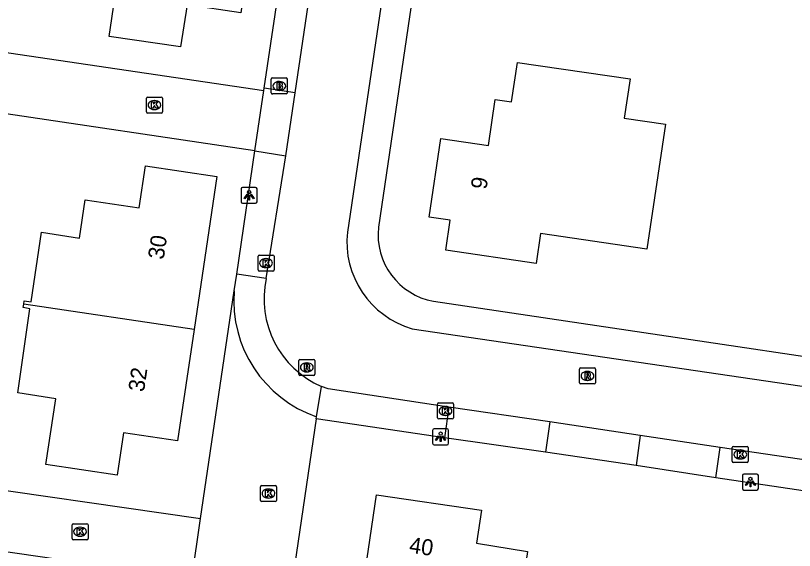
# Model space of a CAD drawing. Extents: x 164150 to 165261, y 382513 to 383432.
# Drawn here: x 164528.83 to 164577.45, y 383053.88 to 383087.26 of the extents above; entities that cross this region are included whole.
import ezdxf

# ---------------------------------------------------------------- set-up
doc = ezdxf.new("R2010")
doc.units = 0
for name, color, linetype in [('IMGEO_Brandkraan', 7, 'Continuous'), ('IMGEO_Kolk', 7, 'Continuous'), ('IMGEO_Lichtpunt', 7, 'Continuous'), ('IMGEO_Pand', 7, 'Continuous'), ('IMGEO_Pand_nummerreeks', 7, 'Continuous'), ('IMGEO_Parkeervlak_open', 7, 'Continuous'), ('IMGEO_Rijbaan_lokaal_open', 7, 'Continuous'), ('IMGEO_Rioolput', 7, 'Continuous'), ('IMGEO_Voetpad_gesloten', 7, 'Continuous'), ('IMGEO_Voetpad_open', 7, 'Continuous')]:
    doc.layers.add(name, color=color, linetype=linetype)

msp = doc.modelspace()

# ---------------------------------------------------------------- linework, layer by layer
at = {"layer": 'IMGEO_Brandkraan'}
for p, q in [((164544.79, 383082.444), (164544.79, 383083.296)), ((164544.865, 383083.37), (164545.717, 383083.37)), ((164545.791, 383083.296), (164545.791, 383082.444)), ((164545.278, 383083.15), (164545.303, 383083.15)), ((164545.717, 383082.37), (164544.865, 383082.37)), ((164545.301, 383082.59), (164545.276, 383082.59))]:
    msp.add_line(p, q, dxfattribs=at)
for points in [[(164544.79, 383082.444), (164544.79, 383083.296)], [(164544.865, 383083.37), (164545.717, 383083.37)], [(164545.791, 383083.296), (164545.791, 383082.444)], [(164545.138, 383083.07), (164545.138, 383082.67), (164545.351, 383082.67)], [(164545.369, 383083.07), (164545.138, 383083.07)], [(164545.317, 383082.989), (164545.263, 383082.989), (164545.263, 383082.913)], [(164545.263, 383082.913), (164545.316, 383082.913)], [(164545.325, 383082.837), (164545.263, 383082.837), (164545.263, 383082.756)], [(164545.717, 383082.37), (164544.865, 383082.37)], [(164545.263, 383082.756), (164545.325, 383082.756)]]:
    msp.add_lwpolyline(points, dxfattribs=at)
for centre, radius, start, end in [((164544.867, 383083.294), 0.0765, 91.552, 178.448), ((164544.867, 383083.294), 0.0765, 91.552, 178.448), ((164545.715, 383083.294), 0.0765, 1.552, 88.448), ((164545.715, 383083.294), 0.0765, 1.552, 88.448), ((164545.318, 383082.951), 0.0379, 267.8285, 90.9355), ((164545.326, 383082.796), 0.0404, 269.8759, 90.5077), ((164545.373, 383082.925), 0.145, 59.4692, 91.5367), ((164545.398, 383082.972), 0.0922, 285.5137, 58.1501), ((164545.403, 383082.78), 0.105, 301.3115, 78.989), ((164544.867, 383082.446), 0.0765, 181.552, 268.448), ((164544.867, 383082.446), 0.0765, 181.552, 268.448), ((164545.357, 383082.921), 0.251, 268.6676, 293.5347), ((164545.715, 383082.446), 0.0765, 271.552, 358.448), ((164545.715, 383082.446), 0.0765, 271.552, 358.448)]:
    msp.add_arc(centre, radius, start, end, dxfattribs=at)
for centre, major_axis, ratio, start_param, end_param in [((164545.277, 383082.87), (-0.387, 0.002), 0.722429, 4.712389, 7.853982), ((164545.302, 383082.87), (-0.39, 0.002), 0.717154, 1.570796, 4.712389)]:
    msp.add_ellipse(centre, major_axis=major_axis, ratio=ratio, start_param=start_param, end_param=end_param, dxfattribs=at)
at = {"layer": 'IMGEO_Kolk'}
for p, q in [((164536.995, 383081.255), (164536.995, 383082.107)), ((164537.07, 383082.181), (164537.922, 383082.181)), ((164537.483, 383081.961), (164537.508, 383081.961)), ((164537.996, 383082.107), (164537.996, 383081.255)), ((164537.506, 383081.401), (164537.481, 383081.401)), ((164537.922, 383081.181), (164537.07, 383081.181)), ((164543.964, 383071.388), (164543.964, 383072.24)), ((164544.039, 383072.314), (164544.891, 383072.314)), ((164544.965, 383072.24), (164544.965, 383071.388)), ((164544.452, 383072.094), (164544.477, 383072.094)), ((164544.891, 383071.314), (164544.039, 383071.314)), ((164544.475, 383071.534), (164544.45, 383071.534)), ((164555.163, 383062.163), (164555.163, 383063.015)), ((164555.238, 383063.089), (164556.09, 383063.089)), ((164555.651, 383062.869), (164555.676, 383062.869)), ((164556.164, 383063.015), (164556.164, 383062.163)), ((164556.09, 383062.089), (164555.238, 383062.089)), ((164555.674, 383062.309), (164555.649, 383062.309)), ((164573.565, 383059.447), (164573.565, 383060.299)), ((164573.64, 383060.373), (164574.492, 383060.373)), ((164574.053, 383060.153), (164574.078, 383060.153)), ((164574.566, 383060.299), (164574.566, 383059.447)), ((164574.076, 383059.593), (164574.051, 383059.593)), ((164574.492, 383059.373), (164573.64, 383059.373)), ((164544.112, 383057.01), (164544.112, 383057.862)), ((164544.187, 383057.936), (164545.039, 383057.936)), ((164544.6, 383057.716), (164544.625, 383057.716)), ((164545.113, 383057.862), (164545.113, 383057.01)), ((164544.623, 383057.156), (164544.598, 383057.156)), ((164545.039, 383056.936), (164544.187, 383056.936)), ((164532.353, 383054.628), (164532.353, 383055.48)), ((164532.428, 383055.554), (164533.28, 383055.554)), ((164532.841, 383055.334), (164532.866, 383055.334)), ((164533.354, 383055.48), (164533.354, 383054.628)), ((164532.864, 383054.774), (164532.839, 383054.774)), ((164533.28, 383054.554), (164532.428, 383054.554))]:
    msp.add_line(p, q, dxfattribs=at)
for points in [[(164536.995, 383081.255), (164536.995, 383082.107)], [(164537.07, 383082.181), (164537.922, 383082.181)], [(164537.316, 383081.881), (164537.439, 383081.881), (164537.439, 383081.73), (164537.569, 383081.881), (164537.733, 383081.881), (164537.587, 383081.73), (164537.74, 383081.481), (164537.588, 383081.481), (164537.503, 383081.645), (164537.439, 383081.578), (164537.439, 383081.481), (164537.316, 383081.481), (164537.316, 383081.881)], [(164537.996, 383082.107), (164537.996, 383081.255)], [(164537.922, 383081.181), (164537.07, 383081.181)], [(164543.964, 383071.388), (164543.964, 383072.24)], [(164544.039, 383072.314), (164544.891, 383072.314)], [(164544.965, 383072.24), (164544.965, 383071.388)], [(164544.285, 383072.014), (164544.408, 383072.014), (164544.408, 383071.863), (164544.538, 383072.014), (164544.702, 383072.014), (164544.556, 383071.863), (164544.709, 383071.614), (164544.557, 383071.614), (164544.472, 383071.778), (164544.408, 383071.711), (164544.408, 383071.614), (164544.285, 383071.614), (164544.285, 383072.014)], [(164544.891, 383071.314), (164544.039, 383071.314)], [(164555.163, 383062.163), (164555.163, 383063.015)], [(164555.238, 383063.089), (164556.09, 383063.089)], [(164556.164, 383063.015), (164556.164, 383062.163)], [(164555.484, 383062.789), (164555.607, 383062.789), (164555.607, 383062.638), (164555.737, 383062.789), (164555.901, 383062.789), (164555.755, 383062.638), (164555.908, 383062.389), (164555.756, 383062.389), (164555.671, 383062.553), (164555.607, 383062.486), (164555.607, 383062.389), (164555.484, 383062.389), (164555.484, 383062.789)], [(164556.09, 383062.089), (164555.238, 383062.089)], [(164573.565, 383059.447), (164573.565, 383060.299)], [(164573.64, 383060.373), (164574.492, 383060.373)], [(164573.886, 383060.073), (164574.009, 383060.073), (164574.009, 383059.922), (164574.139, 383060.073), (164574.303, 383060.073), (164574.157, 383059.922), (164574.31, 383059.673), (164574.158, 383059.673), (164574.073, 383059.837), (164574.009, 383059.77), (164574.009, 383059.673), (164573.886, 383059.673), (164573.886, 383060.073)], [(164574.566, 383060.299), (164574.566, 383059.447)], [(164574.492, 383059.373), (164573.64, 383059.373)], [(164544.112, 383057.01), (164544.112, 383057.862)], [(164544.187, 383057.936), (164545.039, 383057.936)], [(164544.433, 383057.636), (164544.556, 383057.636), (164544.556, 383057.485), (164544.686, 383057.636), (164544.85, 383057.636), (164544.704, 383057.485), (164544.857, 383057.236), (164544.705, 383057.236), (164544.62, 383057.4), (164544.556, 383057.333), (164544.556, 383057.236), (164544.433, 383057.236), (164544.433, 383057.636)], [(164545.113, 383057.862), (164545.113, 383057.01)], [(164545.039, 383056.936), (164544.187, 383056.936)], [(164532.353, 383054.628), (164532.353, 383055.48)], [(164532.428, 383055.554), (164533.28, 383055.554)], [(164532.674, 383055.254), (164532.797, 383055.254), (164532.797, 383055.103), (164532.927, 383055.254), (164533.091, 383055.254), (164532.945, 383055.103), (164533.098, 383054.854), (164532.946, 383054.854), (164532.861, 383055.018), (164532.797, 383054.951), (164532.797, 383054.854), (164532.674, 383054.854), (164532.674, 383055.254)], [(164533.354, 383055.48), (164533.354, 383054.628)], [(164533.28, 383054.554), (164532.428, 383054.554)]]:
    msp.add_lwpolyline(points, dxfattribs=at)
for centre, start, end in [((164537.072, 383082.105), 91.552, 178.448), ((164537.072, 383082.105), 91.552, 178.448), ((164537.92, 383082.105), 1.552, 88.448), ((164537.92, 383082.105), 1.552, 88.448), ((164537.072, 383081.257), 181.552, 268.448), ((164537.072, 383081.257), 181.552, 268.448), ((164537.92, 383081.257), 271.552, 358.448), ((164537.92, 383081.257), 271.552, 358.448), ((164544.041, 383072.238), 91.552, 178.448), ((164544.041, 383072.238), 91.552, 178.448), ((164544.889, 383072.238), 1.552, 88.448), ((164544.889, 383072.238), 1.552, 88.448), ((164544.041, 383071.39), 181.552, 268.448), ((164544.041, 383071.39), 181.552, 268.448), ((164544.889, 383071.39), 271.552, 358.448), ((164544.889, 383071.39), 271.552, 358.448), ((164555.24, 383063.013), 91.552, 178.448), ((164555.24, 383063.013), 91.552, 178.448), ((164556.088, 383063.013), 1.552, 88.448), ((164556.088, 383063.013), 1.552, 88.448), ((164555.24, 383062.165), 181.552, 268.448), ((164555.24, 383062.165), 181.552, 268.448), ((164556.088, 383062.165), 271.552, 358.448), ((164556.088, 383062.165), 271.552, 358.448), ((164573.642, 383060.297), 91.552, 178.448), ((164573.642, 383060.297), 91.552, 178.448), ((164574.49, 383060.297), 1.552, 88.448), ((164574.49, 383060.297), 1.552, 88.448), ((164573.642, 383059.449), 181.552, 268.448), ((164573.642, 383059.449), 181.552, 268.448), ((164574.49, 383059.449), 271.552, 358.448), ((164574.49, 383059.449), 271.552, 358.448), ((164544.189, 383057.86), 91.552, 178.448), ((164544.189, 383057.86), 91.552, 178.448), ((164545.037, 383057.86), 1.552, 88.448), ((164545.037, 383057.86), 1.552, 88.448), ((164544.189, 383057.012), 181.552, 268.448), ((164544.189, 383057.012), 181.552, 268.448), ((164545.037, 383057.012), 271.552, 358.448), ((164545.037, 383057.012), 271.552, 358.448), ((164532.43, 383055.478), 91.552, 178.448), ((164532.43, 383055.478), 91.552, 178.448), ((164533.278, 383055.478), 1.552, 88.448), ((164533.278, 383055.478), 1.552, 88.448), ((164532.43, 383054.63), 181.552, 268.448), ((164532.43, 383054.63), 181.552, 268.448), ((164533.278, 383054.63), 271.552, 358.448), ((164533.278, 383054.63), 271.552, 358.448)]:
    msp.add_arc(centre, 0.0765, start, end, dxfattribs=at)
for centre, major_axis, ratio, start_param, end_param in [((164537.482, 383081.681), (-0.387, 0.002), 0.722429, 4.712389, 7.853982), ((164537.507, 383081.681), (-0.39, 0.002), 0.717154, 1.570796, 4.712389), ((164544.451, 383071.814), (-0.387, 0.002), 0.722429, 4.712389, 7.853982), ((164544.476, 383071.814), (-0.39, 0.002), 0.717154, 1.570796, 4.712389), ((164555.65, 383062.589), (-0.387, 0.002), 0.722429, 4.712389, 7.853982), ((164555.675, 383062.589), (-0.39, 0.002), 0.717154, 1.570796, 4.712389), ((164574.052, 383059.873), (-0.387, 0.002), 0.722429, 4.712389, 7.853982), ((164574.077, 383059.873), (-0.39, 0.002), 0.717154, 1.570796, 4.712389), ((164544.599, 383057.436), (-0.387, 0.002), 0.722429, 4.712389, 7.853982), ((164544.624, 383057.436), (-0.39, 0.002), 0.717154, 1.570796, 4.712389), ((164532.84, 383055.054), (-0.387, 0.002), 0.722429, 4.712389, 7.853982), ((164532.865, 383055.054), (-0.39, 0.002), 0.717154, 1.570796, 4.712389)]:
    msp.add_ellipse(centre, major_axis=major_axis, ratio=ratio, start_param=start_param, end_param=end_param, dxfattribs=at)
at = {"layer": 'IMGEO_Lichtpunt'}
for p, q in [((164543.808, 383076.544), (164543, 383076.544)), ((164543.808, 383076.544), (164543, 383076.544)), ((164542.906, 383076.449), (164542.906, 383075.642)), ((164542.906, 383076.449), (164542.906, 383075.642)), ((164543.902, 383075.642), (164543.902, 383076.449)), ((164543.902, 383075.642), (164543.902, 383076.449)), ((164543, 383075.548), (164543.808, 383075.548)), ((164543, 383075.548), (164543.808, 383075.548)), ((164555.763, 383061.474), (164554.955, 383061.474)), ((164555.763, 383061.474), (164554.955, 383061.474)), ((164554.861, 383061.379), (164554.861, 383060.572)), ((164554.861, 383061.379), (164554.861, 383060.572)), ((164555.857, 383060.572), (164555.857, 383061.379)), ((164555.857, 383060.572), (164555.857, 383061.379)), ((164554.955, 383060.478), (164555.763, 383060.478)), ((164554.955, 383060.478), (164555.763, 383060.478)), ((164574.199, 383058.556), (164574.199, 383057.749)), ((164574.199, 383058.556), (164574.199, 383057.749)), ((164575.101, 383058.651), (164574.293, 383058.651)), ((164575.101, 383058.651), (164574.293, 383058.651)), ((164575.195, 383057.749), (164575.195, 383058.556)), ((164575.195, 383057.749), (164575.195, 383058.556)), ((164574.293, 383057.655), (164575.101, 383057.655)), ((164574.293, 383057.655), (164575.101, 383057.655))]:
    msp.add_line(p, q, dxfattribs=at)
for points in [[(164543.28, 383076.113), (164543.319, 383076.085), (164543.131, 383075.823), (164543.093, 383075.85), (164543.28, 383076.113)], [(164543.382, 383076.065), (164543.429, 383076.065), (164543.429, 383075.743), (164543.382, 383075.743), (164543.382, 383076.065)], [(164543.492, 383076.085), (164543.53, 383076.112), (164543.717, 383075.85), (164543.678, 383075.822), (164543.492, 383076.085)], [(164555.235, 383061.043), (164555.274, 383061.015), (164555.086, 383060.753), (164555.048, 383060.78), (164555.235, 383061.043)], [(164555.337, 383060.995), (164555.384, 383060.995), (164555.384, 383060.673), (164555.337, 383060.673), (164555.337, 383060.995)], [(164555.447, 383061.015), (164555.485, 383061.042), (164555.672, 383060.78), (164555.633, 383060.752), (164555.447, 383061.015)], [(164574.573, 383058.22), (164574.612, 383058.192), (164574.424, 383057.93), (164574.386, 383057.957), (164574.573, 383058.22)], [(164574.675, 383058.172), (164574.722, 383058.172), (164574.722, 383057.85), (164574.675, 383057.85), (164574.675, 383058.172)], [(164574.785, 383058.192), (164574.823, 383058.219), (164575.01, 383057.957), (164574.971, 383057.929), (164574.785, 383058.192)]]:
    msp.add_lwpolyline(points, dxfattribs=at)
for centre in [(164543.405, 383076.247), (164555.36, 383061.177), (164574.698, 383058.354)]:
    msp.add_circle(centre, 0.0994, dxfattribs=at)
for centre, start, end in [((164543, 383076.449), 90, 180), ((164543, 383076.449), 90, 180), ((164543.808, 383076.449), 0, 90), ((164543.808, 383076.449), 0, 90), ((164543, 383075.642), 180, 270), ((164543, 383075.642), 180, 270), ((164543.808, 383075.642), 270, 0), ((164543.808, 383075.642), 270, 360), ((164554.955, 383061.379), 90, 180), ((164554.955, 383061.379), 90, 180), ((164555.763, 383061.379), 0, 90), ((164555.763, 383061.379), 0, 90), ((164554.955, 383060.572), 180, 270), ((164554.955, 383060.572), 180, 270), ((164555.763, 383060.572), 270, 0), ((164555.763, 383060.572), 270, 360), ((164574.293, 383058.556), 90, 180), ((164574.293, 383058.556), 90, 180), ((164575.101, 383058.556), 0, 90), ((164575.101, 383058.556), 0, 90), ((164574.293, 383057.749), 180, 270), ((164574.293, 383057.749), 180, 270), ((164575.101, 383057.749), 270, 0), ((164575.101, 383057.749), 270, 360)]:
    msp.add_arc(centre, 0.0946, start, end, dxfattribs=at)
at = {"layer": 'IMGEO_Pand'}
for points in [[(164543.918, 383094.38), (164542.889, 383087.434), (164539.529, 383087.938), (164539.13, 383085.305), (164534.674, 383085.96), (164536.085, 383095.54)], [(164568.223, 383072.695), (164561.597, 383073.667), (164561.322, 383071.792), (164555.683, 383072.62), (164555.958, 383074.495), (164554.65, 383074.687), (164555.383, 383079.585), (164558.349, 383079.164), (164558.772, 383082.031), (164559.791, 383081.882), (164560.152, 383084.346), (164567.188, 383083.316), (164566.827, 383080.852), (164569.39, 383080.477), (164568.223, 383072.695)], [(164529.333, 383069.246), (164529.365, 383069.464), (164529.791, 383069.399), (164530.438, 383073.745), (164532.811, 383073.374), (164533.169, 383075.763), (164536.541, 383075.262), (164536.934, 383077.884), (164541.395, 383077.23), (164539.973, 383067.665)], [(164539.973, 383067.665), (164538.942, 383060.724), (164535.564, 383061.215), (164535.169, 383058.591), (164530.723, 383059.24), (164531.332, 383063.353), (164528.963, 383063.724), (164529.727, 383068.97), (164529.301, 383069.037), (164529.333, 383069.246)], [(164539.973, 383067.665), (164529.333, 383069.246)], [(164559.792, 383047.101), (164556.617, 383047.571), (164556.31, 383045.494), (164552.551, 383046.05), (164549.751, 383046.465), (164551.363, 383057.356), (164557.915, 383056.397), (164557.603, 383054.329), (164560.784, 383053.825), (164559.792, 383047.101)]]:
    msp.add_lwpolyline(points, dxfattribs=at)
at = {"layer": 'IMGEO_Parkeervlak_open'}
for points in [[(164544.353, 383082.732), (164547.655, 383104.909)], [(164542.642, 383071.119), (164543.77, 383078.815)], [(164555.592, 383060.91), (164547.597, 383062.105)], [(164567.568, 383059.175), (164561.903, 383060.016)], [(164588.211, 383056.086), (164572.546, 383058.416)]]:
    msp.add_lwpolyline(points, dxfattribs=at)
at = {"layer": 'IMGEO_Rijbaan_lokaal_open'}
for points in [[(164564, 383171.523), (164549.539, 383073.752)], [(164546.273, 383082.437), (164549.572, 383104.624)], [(164543.77, 383078.815), (164527.251, 383081.278), (164527.096, 383080.294), (164518.396, 383081.622), (164519.234, 383087.238), (164527.964, 383085.921), (164527.82, 383085.027), (164544.333, 383082.591)], [(164543.77, 383078.815), (164544.333, 383082.591)], [(164545.694, 383078.509), (164546.273, 383082.437)], [(164544.478, 383070.86), (164545.694, 383078.509)], [(164540.378, 383055.886), (164542.471, 383070.08)], [(164553.594, 383067.724), (164596.181, 383061.451)], [(164555.881, 383062.825), (164548.333, 383063.965), (164547.931, 383064.12)], [(164562.174, 383061.911), (164555.881, 383062.825)], [(164547.597, 383062.105), (164543.882, 383036.919)], [(164547.597, 383062.105), (164547.617, 383062.227)], [(164567.813, 383061.059), (164562.174, 383061.911)], [(164572.816, 383060.315), (164567.813, 383061.059)], [(164539.82, 383052.102), (164523.309, 383054.494), (164523.162, 383053.567), (164514.538, 383054.823), (164515.325, 383060.467), (164524.006, 383059.166), (164523.899, 383058.249), (164540.378, 383055.886)], [(164588.521, 383057.995), (164572.816, 383060.315)], [(164539.82, 383052.102), (164540.378, 383055.886)]]:
    msp.add_lwpolyline(points, dxfattribs=at)
for centre, radius, start, end in [((164555.144, 383073.145), 5.638, 173.8159, 254.0411), ((164550.265, 383069.57), 5.929, 167.4325, 246.821), ((164550.111, 383069.474), 7.664, 175.4662, 251.0067)]:
    msp.add_arc(centre, radius, start, end, dxfattribs=at)
at = {"layer": 'IMGEO_Rioolput'}
for p, q in [((164546.581, 383065.808), (164547.433, 383065.808)), ((164546.506, 383064.882), (164546.506, 383065.734)), ((164546.994, 383065.588), (164547.019, 383065.588)), ((164547.507, 383065.734), (164547.507, 383064.882)), ((164547.433, 383064.808), (164546.581, 383064.808)), ((164547.017, 383065.028), (164546.992, 383065.028)), ((164564.025, 383064.349), (164564.025, 383065.201)), ((164564.1, 383065.275), (164564.952, 383065.275)), ((164564.513, 383065.055), (164564.538, 383065.055)), ((164565.026, 383065.201), (164565.026, 383064.349)), ((164564.536, 383064.495), (164564.511, 383064.495)), ((164564.952, 383064.275), (164564.1, 383064.275))]:
    msp.add_line(p, q, dxfattribs=at)
for points in [[(164546.581, 383065.808), (164547.433, 383065.808)], [(164546.506, 383064.882), (164546.506, 383065.734)], [(164547.095, 383065.506), (164546.843, 383065.508), (164546.843, 383065.108)], [(164547.021, 383065.427), (164546.967, 383065.427), (164546.967, 383065.346)], [(164546.967, 383065.346), (164547.019, 383065.346)], [(164547.507, 383065.734), (164547.507, 383064.882)], [(164547.433, 383064.808), (164546.581, 383064.808)], [(164546.843, 383065.108), (164546.967, 383065.108), (164546.967, 383065.27), (164546.978, 383065.27)], [(164547.025, 383065.241), (164547.096, 383065.108), (164547.236, 383065.108), (164547.171, 383065.234)], [(164564.025, 383064.349), (164564.025, 383065.201)], [(164564.1, 383065.275), (164564.952, 383065.275)], [(164564.614, 383064.973), (164564.362, 383064.975), (164564.362, 383064.575)], [(164564.54, 383064.894), (164564.486, 383064.894), (164564.486, 383064.813)], [(164564.486, 383064.813), (164564.538, 383064.813)], [(164565.026, 383065.201), (164565.026, 383064.349)], [(164564.362, 383064.575), (164564.486, 383064.575), (164564.486, 383064.737), (164564.497, 383064.737)], [(164564.544, 383064.708), (164564.615, 383064.575), (164564.755, 383064.575), (164564.69, 383064.701)], [(164564.952, 383064.275), (164564.1, 383064.275)]]:
    msp.add_lwpolyline(points, dxfattribs=at)
for centre, radius, start, end in [((164546.583, 383065.732), 0.0765, 91.552, 178.448), ((164546.583, 383065.732), 0.0765, 91.552, 178.448), ((164547.431, 383065.732), 0.0765, 1.552, 88.448), ((164547.431, 383065.732), 0.0765, 1.552, 88.448), ((164547.003, 383065.535), 0.19, 274.7715, 282.9687), ((164547.027, 383065.331), 0.0964, 77.0061, 93.1865), ((164547.041, 383065.388), 0.0378, 276.6634, 79.6772), ((164547.094, 383065.396), 0.109, 350.3612, 89.416), ((164547.092, 383065.396), 0.112, 277.5842, 350.9817), ((164546.583, 383064.884), 0.0765, 181.552, 268.448), ((164546.583, 383064.884), 0.0765, 181.552, 268.448), ((164546.977, 383065.217), 0.0533, 26.0293, 88.6989), ((164547.076, 383065.181), 0.108, 29.5134, 73.7905), ((164547.431, 383064.884), 0.0765, 271.552, 358.448), ((164547.431, 383064.884), 0.0765, 271.552, 358.448), ((164564.102, 383065.199), 0.0765, 91.552, 178.448), ((164564.102, 383065.199), 0.0765, 91.552, 178.448), ((164564.522, 383065.002), 0.19, 274.7715, 282.9687), ((164564.546, 383064.798), 0.0964, 77.0061, 93.1865), ((164564.56, 383064.855), 0.0378, 276.6634, 79.6772), ((164564.613, 383064.863), 0.109, 350.3612, 89.416), ((164564.611, 383064.863), 0.112, 277.5842, 350.9817), ((164564.95, 383065.199), 0.0765, 1.552, 88.448), ((164564.95, 383065.199), 0.0765, 1.552, 88.448), ((164564.102, 383064.351), 0.0765, 181.552, 268.448), ((164564.102, 383064.351), 0.0765, 181.552, 268.448), ((164564.496, 383064.684), 0.0533, 26.0293, 88.6989), ((164564.595, 383064.648), 0.108, 29.5134, 73.7905), ((164564.95, 383064.351), 0.0765, 271.552, 358.448), ((164564.95, 383064.351), 0.0765, 271.552, 358.448)]:
    msp.add_arc(centre, radius, start, end, dxfattribs=at)
for centre, major_axis, ratio, start_param, end_param in [((164546.993, 383065.308), (-0.387, 0.002), 0.722429, 4.712389, 7.853982), ((164547.018, 383065.308), (-0.39, 0.002), 0.717154, 1.570796, 4.712389), ((164564.512, 383064.775), (-0.387, 0.002), 0.722429, 4.712389, 7.853982), ((164564.537, 383064.775), (-0.39, 0.002), 0.717154, 1.570796, 4.712389)]:
    msp.add_ellipse(centre, major_axis=major_axis, ratio=ratio, start_param=start_param, end_param=end_param, dxfattribs=at)
at = {"layer": 'IMGEO_Voetpad_gesloten'}
for points in [[(164565.828, 383171.331), (164551.479, 383074.055)], [(164554.918, 383069.432), (164596.268, 383063.274)]]:
    msp.add_lwpolyline(points, dxfattribs=at)
msp.add_arc((164555.692, 383073.598), 4.238, 173.8146, 259.4757, dxfattribs=at)
at = {"layer": 'IMGEO_Voetpad_open'}
for points in [[(164544.333, 383082.591), (164544.353, 383082.732)], [(164546.273, 383082.437), (164544.353, 383082.732)], [(164543.77, 383078.815), (164545.694, 383078.509)], [(164542.471, 383070.08), (164542.642, 383071.119)], [(164544.478, 383070.86), (164542.642, 383071.119)], [(164547.617, 383062.227), (164547.931, 383064.12)], [(164555.881, 383062.825), (164555.592, 383060.91)], [(164562.174, 383061.911), (164561.903, 383060.016)], [(164567.813, 383061.059), (164567.568, 383059.175)], [(164561.903, 383060.016), (164555.592, 383060.91)], [(164572.546, 383058.416), (164572.816, 383060.315)], [(164572.546, 383058.416), (164567.568, 383059.175)]]:
    msp.add_lwpolyline(points, dxfattribs=at)

# ---------------------------------------------------------------- texts
at = {"layer": 'IMGEO_Pand_nummerreeks'}
for s, rotation, p in [('9', 81.4861, (164558.22, 383076.378)), ('30', 81.5477, (164538.071, 383072.006)), ('32', 81.5477, (164536.843, 383063.744)), ('40', 351.6763, (164553.353, 383053.75))]:
    msp.add_text(s, height=1, rotation=rotation, dxfattribs=at).set_placement(p)

doc.saveas('drawing.dxf')
